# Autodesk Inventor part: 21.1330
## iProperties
Created: 2006-12
Part Number: 21.1330
Document SubType Name: Modeling
Designer: Andy Moles
Material: Steel, Mild
Mass: 4.94212 g
Surface Area: 5.644 cm^2
Volume: 0.628768 cm^3
Density: 7.86 g/cm^3
Description: M6 SQUARE NUT
Vendor: S
Author: Andy Moles
Title: M6 SQUARE NUT
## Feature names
1. Extrusion1
2. Revolution1
